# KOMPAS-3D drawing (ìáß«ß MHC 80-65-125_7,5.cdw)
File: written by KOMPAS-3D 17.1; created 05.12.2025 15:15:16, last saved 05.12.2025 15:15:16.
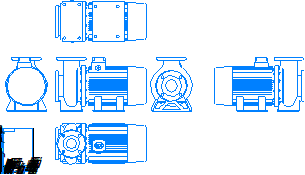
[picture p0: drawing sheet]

Sheet 1: A4, portrait

Title block, sheet 1: name: Насос MHC / 80-65-125_7,5; material: Сталь 10  ГОСТ 1050-88; mass: 193,06; sheets: 1; sheet format: A4

Views: Проекционный вид 2, Проекционный вид 3, Проекционный вид 4, Проекционный вид 5, Проекционный вид 6
Referenced files in \\adlc.lan\data\АДЛ_ПКД\3D-модели\ADL production\Насосы ГРАНПАМП\Насосы ГРАНПАМП серии МНС\KOMPAS 3D\: Насос МНС 80-65-125_7,5.m3d
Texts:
  Andrey
  АДЛ
Dimensions and other numbers on the sheet: 1:1; 1; 80-65-125_7,5; 193,06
